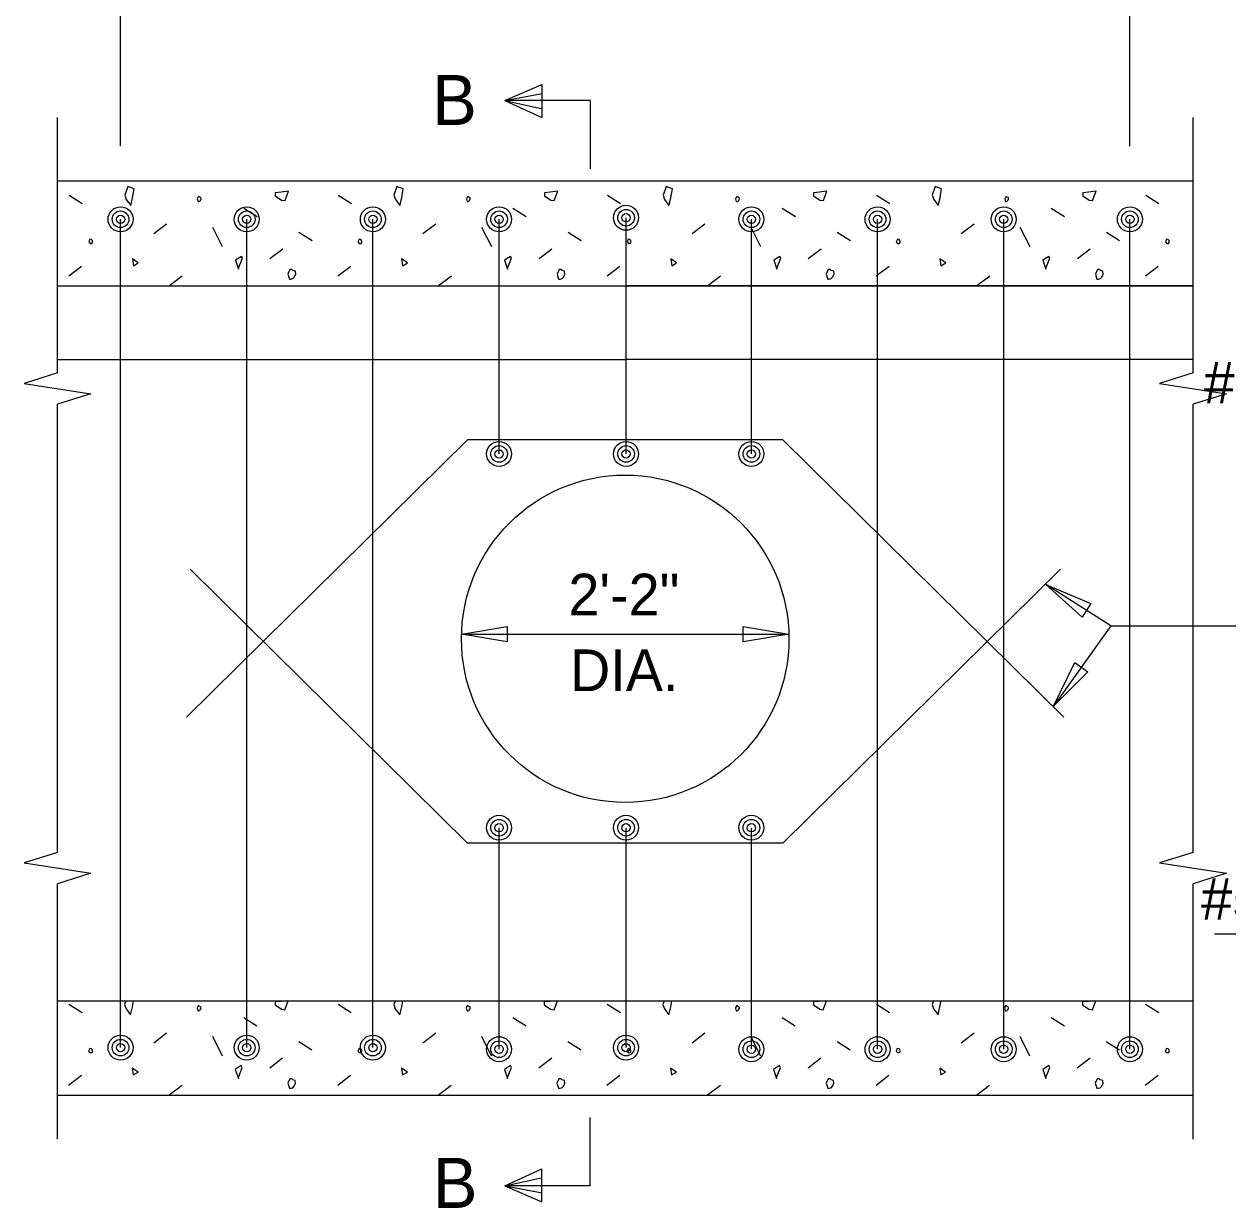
# Model space of a CAD drawing. Extents: x 0 to 34, y 0 to 23.5.
# Drawn here: x 25.268 to 29.778, y 4.725 to 9.162 of the extents above; entities that cross this region are included whole.
import ezdxf

# ---------------------------------------------------------------- set-up
doc = ezdxf.new("R2010")
doc.units = 0
for name, color, linetype in [('BRDG_ANNO_General-Notes', 7, 'Continuous'), ('BRDG_BASE_Obj-Line', 7, 'Continuous'), ('BRDG_BASE_Pattern', 7, 'Continuous'), ('BRDG_BASE_Rebar', 7, 'Continuous')]:
    doc.layers.add(name, color=color, linetype=linetype)

msp = doc.modelspace()

# ---------------------------------------------------------------- linework, layer by layer
at = {"layer": 'BRDG_ANNO_General-Notes'}
for p, q in [((25.6297, 8.7046), (25.6297, 9.5776)), ((29.4112, 8.7046), (29.4112, 9.5776)), ((27.0696, 8.8753), (27.2082, 8.9354)), ((27.2082, 8.9354), (27.2082, 8.8112)), ((27.0696, 8.8753), (27.2089, 8.901)), ((27.3896, 8.8753), (27.0696, 8.8753)), ((27.0696, 8.8753), (27.2082, 8.8112)), ((27.0696, 8.8753), (27.2059, 8.8456)), ((27.3896, 8.8753), (27.3896, 8.6193)), ((29.3401, 6.9065), (29.0961, 7.0609)), ((29.2322, 6.9393), (29.0961, 7.0609)), ((29.0961, 7.0609), (29.2643, 6.99)), ((29.2643, 6.99), (29.2322, 6.9393)), ((26.907, 6.8751), (27.078, 6.9035)), ((27.078, 6.9035), (27.078, 6.8466)), ((27.9629, 6.8466), (27.9629, 6.9035)), ((27.9629, 6.9035), (28.1339, 6.8751)), ((29.3401, 6.9065), (29.1251, 6.6047)), ((29.3401, 6.9065), (31.0649, 6.9065)), ((26.907, 6.8751), (28.1339, 6.8751)), ((27.078, 6.8466), (26.907, 6.8751)), ((28.1339, 6.8751), (27.9629, 6.8466)), ((29.1251, 6.6047), (29.2051, 6.7687)), ((29.2051, 6.7687), (29.254, 6.7339)), ((29.254, 6.7339), (29.1251, 6.6047)), ((29.728, 5.752), (31.3093, 5.752)), ((27.3896, 4.8077), (27.3896, 5.0637)), ((27.0696, 4.8077), (27.2082, 4.8717)), ((27.2082, 4.7476), (27.2082, 4.8717)), ((27.0696, 4.8077), (27.2059, 4.8373)), ((27.3896, 4.8077), (27.0696, 4.8077)), ((27.0696, 4.8077), (27.2082, 4.7476)), ((27.0696, 4.8077), (27.2089, 4.7819))]:
    msp.add_line(p, q, dxfattribs=at)
at = {"layer": 'BRDG_BASE_Obj-Line'}
for p, q in [((25.3933, 7.8541), (25.3933, 8.8111)), ((29.6476, 7.8541), (29.6476, 8.8111)), ((25.3933, 8.5741), (29.6476, 8.5741)), ((25.3937, 8.1801), (29.6476, 8.1801)), ((29.6468, 8.1801), (27.5267, 8.1801)), ((25.3937, 7.9044), (27.5204, 7.9044)), ((29.6468, 7.9044), (27.5204, 7.9044)), ((25.3933, 7.8541), (25.2683, 7.815)), ((29.6476, 7.8541), (29.5226, 7.815)), ((25.2683, 7.815), (25.5183, 7.7759)), ((29.5226, 7.815), (29.7726, 7.7759)), ((25.5183, 7.7759), (25.3933, 7.7369)), ((29.7726, 7.7759), (29.6476, 7.7369)), ((25.3933, 6.0572), (25.3933, 7.7369)), ((29.6476, 6.0572), (29.6476, 7.7369)), ((25.3933, 6.0572), (25.2683, 6.0181)), ((29.6476, 6.0572), (29.5226, 6.0181)), ((25.2683, 6.0181), (25.5183, 5.9791)), ((29.5226, 6.0181), (29.7726, 5.9791)), ((25.5183, 5.9791), (25.3933, 5.94)), ((29.7726, 5.9791), (29.6476, 5.94)), ((25.3933, 4.983), (25.3933, 5.94)), ((29.6476, 4.983), (29.6476, 5.94)), ((25.3933, 5.5015), (29.6476, 5.5015)), ((25.3933, 5.147), (29.6476, 5.147))]:
    msp.add_line(p, q, dxfattribs=at)
msp.add_circle((27.5204, 6.8578), 0.6135, dxfattribs=at)
at = {"layer": 'BRDG_BASE_Pattern'}
for p, q in [((25.4368, 8.5211), (25.4862, 8.4898)), ((26.4452, 8.5211), (26.4946, 8.4898)), ((27.4536, 8.5211), (27.503, 8.4898)), ((28.462, 8.5211), (28.5114, 8.4898)), ((29.4704, 8.5211), (29.5198, 8.4898)), ((26.0915, 8.472), (26.141, 8.4408)), ((27.0999, 8.472), (27.1494, 8.4408)), ((28.1083, 8.472), (28.1578, 8.4408)), ((29.1167, 8.472), (29.1661, 8.4408)), ((25.8024, 8.4123), (25.7543, 8.3757)), ((25.974, 8.4012), (26.0107, 8.3277)), ((26.8108, 8.4123), (26.7627, 8.3757)), ((26.9824, 8.4012), (27.0191, 8.3277)), ((27.8192, 8.4123), (27.7711, 8.3757)), ((27.9908, 8.4012), (28.0274, 8.3277)), ((28.8276, 8.4123), (28.7795, 8.3757)), ((28.9992, 8.4012), (29.0358, 8.3277)), ((26.2979, 8.3817), (26.3473, 8.3505)), ((27.3062, 8.3817), (27.3557, 8.3505)), ((28.3146, 8.3817), (28.3641, 8.3505)), ((29.323, 8.3817), (29.3725, 8.3505)), ((26.2374, 8.3186), (26.1893, 8.282)), ((27.2458, 8.3186), (27.1977, 8.282)), ((28.2542, 8.3186), (28.206, 8.282)), ((29.2626, 8.3186), (29.2144, 8.282)), ((25.4836, 8.2536), (25.4355, 8.217)), ((26.492, 8.2536), (26.4439, 8.217)), ((27.5004, 8.2536), (27.4523, 8.217)), ((28.5088, 8.2536), (28.4607, 8.217)), ((29.5172, 8.2536), (29.4691, 8.217)), ((25.8608, 8.2167), (25.8127, 8.1801)), ((26.8692, 8.2167), (26.821, 8.1801)), ((27.8776, 8.2167), (27.8294, 8.1801)), ((28.8859, 8.2167), (28.8378, 8.1801)), ((25.4364, 5.4881), (25.4858, 5.4568)), ((26.4448, 5.4881), (26.4942, 5.4568)), ((27.4532, 5.4881), (27.5026, 5.4568)), ((28.4616, 5.4881), (28.511, 5.4568)), ((29.4699, 5.4881), (29.5194, 5.4568)), ((26.0911, 5.439), (26.1406, 5.4078)), ((27.0995, 5.439), (27.149, 5.4078)), ((28.1079, 5.439), (28.1573, 5.4078)), ((29.1162, 5.439), (29.1657, 5.4078)), ((25.802, 5.3793), (25.7539, 5.3427)), ((25.9736, 5.3682), (26.0103, 5.2947)), ((26.8104, 5.3793), (26.7623, 5.3427)), ((26.982, 5.3682), (27.0186, 5.2947)), ((27.8188, 5.3793), (27.7707, 5.3427)), ((27.9904, 5.3682), (28.027, 5.2947)), ((28.8272, 5.3793), (28.7791, 5.3427)), ((28.9987, 5.3682), (29.0354, 5.2947)), ((26.2974, 5.3487), (26.3469, 5.3174)), ((27.3058, 5.3487), (27.3553, 5.3174)), ((28.3142, 5.3487), (28.3637, 5.3174)), ((29.3226, 5.3487), (29.3721, 5.3174)), ((26.237, 5.2856), (26.1889, 5.249)), ((27.2454, 5.2856), (27.1972, 5.249)), ((28.2538, 5.2856), (28.2056, 5.249)), ((29.2621, 5.2856), (29.214, 5.249)), ((25.4832, 5.2206), (25.4351, 5.184)), ((26.4916, 5.2206), (26.4435, 5.184)), ((27.5, 5.2206), (27.4519, 5.184)), ((28.5084, 5.2206), (28.4603, 5.184)), ((29.5168, 5.2206), (29.4686, 5.184)), ((25.8604, 5.1836), (25.8122, 5.147)), ((26.8687, 5.1836), (26.8206, 5.147)), ((27.8771, 5.1836), (27.829, 5.147)), ((28.8855, 5.1836), (28.8374, 5.147))]:
    msp.add_line(p, q, dxfattribs=at)
for points in [[(25.6566, 8.5535), (25.6454, 8.5204), (25.6511, 8.5038), (25.6677, 8.4817), (25.675, 8.5111), (25.6805, 8.5443)], [(26.2312, 8.5316), (26.2092, 8.5297), (26.2092, 8.5186), (26.2331, 8.5021), (26.2461, 8.5003), (26.259, 8.5352)], [(26.665, 8.5535), (26.6538, 8.5204), (26.6595, 8.5038), (26.676, 8.4817), (26.6834, 8.5111), (26.6889, 8.5443)], [(27.2396, 8.5316), (27.2176, 8.5297), (27.2176, 8.5186), (27.2415, 8.5021), (27.2545, 8.5003), (27.2674, 8.5352)], [(27.6734, 8.5535), (27.6622, 8.5204), (27.6679, 8.5038), (27.6844, 8.4817), (27.6918, 8.5111), (27.6973, 8.5443)], [(28.248, 8.5316), (28.2259, 8.5297), (28.2259, 8.5186), (28.2499, 8.5021), (28.2629, 8.5003), (28.2758, 8.5352)], [(28.6818, 8.5535), (28.6706, 8.5204), (28.6762, 8.5038), (28.6928, 8.4817), (28.7002, 8.5111), (28.7057, 8.5443)], [(29.2564, 8.5316), (29.2343, 8.5297), (29.2343, 8.5186), (29.2583, 8.5021), (29.2712, 8.5003), (29.2842, 8.5352)], [(25.917, 8.5062), (25.9199, 8.497), (25.9226, 8.497), (25.9264, 8.498), (25.9291, 8.5006), (25.9317, 8.5062), (25.931, 8.5118), (25.9264, 8.5127), (25.9244, 8.5146), (25.9207, 8.5146)], [(26.9254, 8.5062), (26.9283, 8.497), (26.931, 8.497), (26.9347, 8.498), (26.9374, 8.5006), (26.9401, 8.5062), (26.9394, 8.5118), (26.9347, 8.5127), (26.9328, 8.5146), (26.9291, 8.5146)], [(27.9338, 8.5062), (27.9367, 8.497), (27.9394, 8.497), (27.9431, 8.498), (27.9458, 8.5006), (27.9485, 8.5062), (27.9478, 8.5118), (27.9431, 8.5127), (27.9411, 8.5146), (27.9375, 8.5146)], [(28.9422, 8.5062), (28.9451, 8.497), (28.9478, 8.497), (28.9515, 8.498), (28.9542, 8.5006), (28.9569, 8.5062), (28.9561, 8.5118), (28.9515, 8.5127), (28.9495, 8.5146), (28.9459, 8.5146)], [(25.5151, 8.3556), (25.5105, 8.3455), (25.5159, 8.3398), (25.5225, 8.3398), (25.5252, 8.3428), (25.5252, 8.3482), (25.5243, 8.3509), (25.5215, 8.3539)], [(26.5235, 8.3556), (26.5189, 8.3455), (26.5243, 8.3398), (26.5309, 8.3398), (26.5336, 8.3428), (26.5336, 8.3482), (26.5327, 8.3509), (26.5298, 8.3539)], [(27.5319, 8.3556), (27.5272, 8.3455), (27.5327, 8.3398), (27.5393, 8.3398), (27.542, 8.3428), (27.542, 8.3482), (27.5411, 8.3509), (27.5382, 8.3539)], [(28.5403, 8.3556), (28.5356, 8.3455), (28.541, 8.3398), (28.5477, 8.3398), (28.5504, 8.3428), (28.5504, 8.3482), (28.5495, 8.3509), (28.5466, 8.3539)], [(29.5486, 8.3556), (29.544, 8.3455), (29.5494, 8.3398), (29.556, 8.3398), (29.5587, 8.3428), (29.5587, 8.3482), (29.5579, 8.3509), (29.555, 8.3539)], [(25.674, 8.2819), (25.6777, 8.256), (25.6962, 8.2671)], [(26.0601, 8.2765), (26.0715, 8.2432), (26.0715, 8.2468), (26.0861, 8.2838), (26.0824, 8.2911)], [(26.6824, 8.2819), (26.6861, 8.256), (26.7046, 8.2671)], [(27.0684, 8.2765), (27.0798, 8.2432), (27.0798, 8.2468), (27.0945, 8.2838), (27.0908, 8.2911)], [(27.6908, 8.2819), (27.6945, 8.256), (27.713, 8.2671)], [(28.0768, 8.2765), (28.0882, 8.2432), (28.0882, 8.2468), (28.1029, 8.2838), (28.0992, 8.2911)], [(28.6992, 8.2819), (28.7029, 8.256), (28.7214, 8.2671)], [(29.0852, 8.2765), (29.0966, 8.2432), (29.0966, 8.2468), (29.1113, 8.2838), (29.1076, 8.2911)], [(26.2567, 8.2247), (26.2625, 8.2063), (26.2678, 8.2063), (26.2753, 8.2081), (26.2807, 8.2135), (26.2861, 8.2247), (26.2846, 8.2357), (26.2753, 8.2376), (26.2714, 8.2414), (26.2641, 8.2414)], [(27.2651, 8.2247), (27.2709, 8.2063), (27.2762, 8.2063), (27.2837, 8.2081), (27.2891, 8.2135), (27.2945, 8.2247), (27.293, 8.2357), (27.2837, 8.2376), (27.2798, 8.2414), (27.2724, 8.2414)], [(28.2734, 8.2247), (28.2793, 8.2063), (28.2846, 8.2063), (28.2921, 8.2081), (28.2975, 8.2135), (28.3029, 8.2247), (28.3014, 8.2357), (28.2921, 8.2376), (28.2882, 8.2414), (28.2808, 8.2414)], [(29.2818, 8.2247), (29.2877, 8.2063), (29.293, 8.2063), (29.3005, 8.2081), (29.3059, 8.2135), (29.3112, 8.2247), (29.3097, 8.2357), (29.3005, 8.2376), (29.2966, 8.2414), (29.2892, 8.2414)], [(25.9166, 5.4732), (25.9195, 5.464), (25.9222, 5.464), (25.9259, 5.4649), (25.9286, 5.4676), (25.9313, 5.4732), (25.9306, 5.4787), (25.9259, 5.4797), (25.924, 5.4816), (25.9203, 5.4816)], [(26.925, 5.4732), (26.9279, 5.464), (26.9306, 5.464), (26.9343, 5.4649), (26.937, 5.4676), (26.9397, 5.4732), (26.939, 5.4787), (26.9343, 5.4797), (26.9323, 5.4816), (26.9287, 5.4816)], [(27.9334, 5.4732), (27.9363, 5.464), (27.939, 5.464), (27.9427, 5.4649), (27.9454, 5.4676), (27.9481, 5.4732), (27.9473, 5.4787), (27.9427, 5.4797), (27.9407, 5.4816), (27.9371, 5.4816)], [(28.9418, 5.4732), (28.9447, 5.464), (28.9473, 5.464), (28.9511, 5.4649), (28.9538, 5.4676), (28.9565, 5.4732), (28.9557, 5.4787), (28.9511, 5.4797), (28.9491, 5.4816), (28.9455, 5.4816)], [(25.5147, 5.3226), (25.5101, 5.3124), (25.5155, 5.3068), (25.5221, 5.3068), (25.5248, 5.3098), (25.5248, 5.3152), (25.5239, 5.3179), (25.521, 5.3208)], [(26.5231, 5.3226), (26.5184, 5.3124), (26.5239, 5.3068), (26.5305, 5.3068), (26.5332, 5.3098), (26.5332, 5.3152), (26.5323, 5.3179), (26.5294, 5.3208)], [(27.5315, 5.3226), (27.5268, 5.3124), (27.5322, 5.3068), (27.5389, 5.3068), (27.5416, 5.3098), (27.5416, 5.3152), (27.5407, 5.3179), (27.5378, 5.3208)], [(28.5398, 5.3226), (28.5352, 5.3124), (28.5406, 5.3068), (28.5472, 5.3068), (28.5499, 5.3098), (28.5499, 5.3152), (28.5491, 5.3179), (28.5462, 5.3208)], [(29.5482, 5.3226), (29.5436, 5.3124), (29.549, 5.3068), (29.5556, 5.3068), (29.5583, 5.3098), (29.5583, 5.3152), (29.5574, 5.3179), (29.5546, 5.3208)], [(25.6736, 5.2489), (25.6773, 5.223), (25.6958, 5.2341)], [(26.0596, 5.2434), (26.071, 5.2102), (26.071, 5.2138), (26.0857, 5.2508), (26.082, 5.2581)], [(26.682, 5.2489), (26.6857, 5.223), (26.7042, 5.2341)], [(27.068, 5.2434), (27.0794, 5.2102), (27.0794, 5.2138), (27.0941, 5.2508), (27.0904, 5.2581)], [(27.6904, 5.2489), (27.6941, 5.223), (27.7126, 5.2341)], [(28.0764, 5.2434), (28.0878, 5.2102), (28.0878, 5.2138), (28.1025, 5.2508), (28.0987, 5.2581)], [(28.6988, 5.2489), (28.7024, 5.223), (28.7209, 5.2341)], [(29.0848, 5.2434), (29.0962, 5.2102), (29.0962, 5.2138), (29.1109, 5.2508), (29.1071, 5.2581)], [(26.2562, 5.1917), (26.2621, 5.1733), (26.2674, 5.1733), (26.2749, 5.1751), (26.2803, 5.1805), (26.2857, 5.1917), (26.2842, 5.2027), (26.2749, 5.2046), (26.271, 5.2084), (26.2636, 5.2084)], [(27.2646, 5.1917), (27.2705, 5.1733), (27.2758, 5.1733), (27.2833, 5.1751), (27.2887, 5.1805), (27.2941, 5.1917), (27.2926, 5.2027), (27.2833, 5.2046), (27.2794, 5.2084), (27.272, 5.2084)], [(28.273, 5.1917), (28.2789, 5.1733), (28.2842, 5.1733), (28.2917, 5.1751), (28.2971, 5.1805), (28.3024, 5.1917), (28.3009, 5.2027), (28.2917, 5.2046), (28.2878, 5.2084), (28.2804, 5.2084)], [(29.2814, 5.1917), (29.2872, 5.1733), (29.2926, 5.1733), (29.3001, 5.1751), (29.3055, 5.1805), (29.3108, 5.1917), (29.3093, 5.2027), (29.3001, 5.2046), (29.2961, 5.2084), (29.2888, 5.2084)]]:
    msp.add_lwpolyline(points, close=True, dxfattribs=at)
for points in [[(25.6498, 5.5015), (25.645, 5.4873), (25.6507, 5.4708), (25.6672, 5.4486), (25.6746, 5.4781), (25.6785, 5.5015)], [(26.2308, 5.4985), (26.2087, 5.4967), (26.2087, 5.4856), (26.2327, 5.4691), (26.2457, 5.4672), (26.2583, 5.5015)], [(26.2534, 5.5015), (26.2308, 5.4985)], [(26.6582, 5.5015), (26.6534, 5.4873), (26.6591, 5.4708), (26.6756, 5.4486), (26.683, 5.4781), (26.6869, 5.5015)], [(27.2392, 5.4985), (27.2171, 5.4967), (27.2171, 5.4856), (27.2411, 5.4691), (27.2541, 5.4672), (27.2667, 5.5015)], [(27.2618, 5.5015), (27.2392, 5.4985)], [(27.6666, 5.5015), (27.6618, 5.4873), (27.6674, 5.4708), (27.684, 5.4486), (27.6914, 5.4781), (27.6953, 5.5015)], [(28.2476, 5.4985), (28.2255, 5.4967), (28.2255, 5.4856), (28.2495, 5.4691), (28.2624, 5.4672), (28.2751, 5.5015)], [(28.2702, 5.5015), (28.2476, 5.4985)], [(28.6749, 5.5015), (28.6702, 5.4873), (28.6758, 5.4708), (28.6924, 5.4486), (28.6997, 5.4781), (28.7036, 5.5015)], [(29.256, 5.4985), (29.2339, 5.4967), (29.2339, 5.4856), (29.2579, 5.4691), (29.2708, 5.4672), (29.2835, 5.5015)], [(29.2786, 5.5015), (29.256, 5.4985)]]:
    msp.add_lwpolyline(points, dxfattribs=at)
at = {"layer": 'BRDG_BASE_Rebar'}
for p, q in [((27.5235, 7.5506), (27.5235, 8.4359)), ((25.6297, 5.3254), (25.6297, 8.4301)), ((26.1024, 5.3254), (26.1024, 8.4301)), ((26.575, 5.3254), (26.575, 8.4301)), ((27.0478, 7.5506), (27.0478, 8.4301)), ((27.9931, 7.5506), (27.9931, 8.4301)), ((28.4658, 5.3196), (28.4658, 8.4301)), ((28.9384, 5.3196), (28.9384, 8.4301)), ((29.4112, 5.3196), (29.4112, 8.4301)), ((26.9296, 7.6035), (25.8769, 6.5646)), ((28.1112, 7.6035), (26.9296, 7.6035)), ((28.1112, 7.6035), (29.164, 6.5646)), ((26.9294, 6.0924), (25.8901, 7.1185)), ((28.1114, 6.0924), (29.1508, 7.1185)), ((26.3902, 6.6248), (26.3879, 6.627)), ((28.6507, 6.6248), (28.6529, 6.627)), ((27.0478, 5.3196), (27.0478, 6.1497)), ((27.5235, 5.3254), (27.5235, 6.1497)), ((27.9931, 5.3196), (27.9931, 6.1497)), ((28.1114, 6.0924), (26.9294, 6.0924))]:
    msp.add_line(p, q, dxfattribs=at)
for centre, radius in [((27.5235, 8.4359), 0.0469), ((25.6297, 8.4301), 0.0469), ((25.6297, 8.4301), 0.0312), ((25.6297, 8.4301), 0.0156), ((26.1024, 8.4301), 0.0469), ((26.1024, 8.4301), 0.0312), ((26.1024, 8.4301), 0.0156), ((26.575, 8.4301), 0.0469), ((26.575, 8.4301), 0.0312), ((26.575, 8.4301), 0.0156), ((27.0478, 8.4301), 0.0469), ((27.0478, 8.4301), 0.0312), ((27.0478, 8.4301), 0.0156), ((27.5235, 8.4359), 0.0312), ((27.5235, 8.4359), 0.0156), ((27.9931, 8.4301), 0.0469), ((27.9931, 8.4301), 0.0312), ((27.9931, 8.4301), 0.0156), ((28.4658, 8.4301), 0.0469), ((28.4658, 8.4301), 0.0312), ((28.4658, 8.4301), 0.0156), ((28.9384, 8.4301), 0.0469), ((28.9384, 8.4301), 0.0312), ((28.9384, 8.4301), 0.0156), ((29.4112, 8.4301), 0.0469), ((29.4112, 8.4301), 0.0312), ((29.4112, 8.4301), 0.0156), ((27.0478, 7.5506), 0.0469), ((27.0478, 7.5506), 0.0312), ((27.5235, 7.5506), 0.0469), ((27.5235, 7.5506), 0.0312), ((27.9931, 7.5506), 0.0469), ((27.9931, 7.5506), 0.0312), ((27.0478, 7.5506), 0.0156), ((27.5235, 7.5506), 0.0156), ((27.9931, 7.5506), 0.0156), ((27.0478, 6.1497), 0.0469), ((27.0478, 6.1497), 0.0312), ((27.5235, 6.1497), 0.0469), ((27.5235, 6.1497), 0.0312), ((27.9931, 6.1497), 0.0469), ((27.9931, 6.1497), 0.0312), ((27.0478, 6.1497), 0.0156), ((27.5235, 6.1497), 0.0156), ((27.9931, 6.1497), 0.0156), ((25.6297, 5.3254), 0.0469), ((26.1024, 5.3254), 0.0469), ((26.575, 5.3254), 0.0469), ((27.5235, 5.3254), 0.0469), ((25.6297, 5.3254), 0.0312), ((25.6297, 5.3254), 0.0156), ((26.1024, 5.3254), 0.0312), ((26.1024, 5.3254), 0.0156), ((26.575, 5.3254), 0.0312), ((26.575, 5.3254), 0.0156), ((27.0478, 5.3196), 0.0469), ((27.0478, 5.3196), 0.0312), ((27.0478, 5.3196), 0.0156), ((27.5235, 5.3254), 0.0312), ((27.5235, 5.3254), 0.0156), ((27.9931, 5.3196), 0.0469), ((27.9931, 5.3196), 0.0312), ((27.9931, 5.3196), 0.0156), ((28.4658, 5.3196), 0.0469), ((28.4658, 5.3196), 0.0312), ((28.4658, 5.3196), 0.0156), ((28.9384, 5.3196), 0.0469), ((28.9384, 5.3196), 0.0312), ((28.9384, 5.3196), 0.0156), ((29.4112, 5.3196), 0.0469), ((29.4112, 5.3196), 0.0312), ((29.4112, 5.3196), 0.0156)]:
    msp.add_circle(centre, radius, dxfattribs=at)

# ---------------------------------------------------------------- texts
at = {"layer": 'BRDG_ANNO_General-Notes'}
for s, height, p in [('B', 0.1875, (26.7972, 8.7837)), ('#5 STIRRUPS', 0.15625, (29.6876, 7.7398)), ('2\'-2"', 0.15625, (27.3075, 6.9455)), ('DIA.', 0.15625, (27.3135, 6.6616)), ('#5 STIRRUPS', 0.15625, (29.6783, 5.8047)), ('B', 0.1875, (26.7996, 4.7247))]:
    msp.add_text(s, height=height, dxfattribs=at).set_placement(p)

doc.saveas('drawing.dxf')
